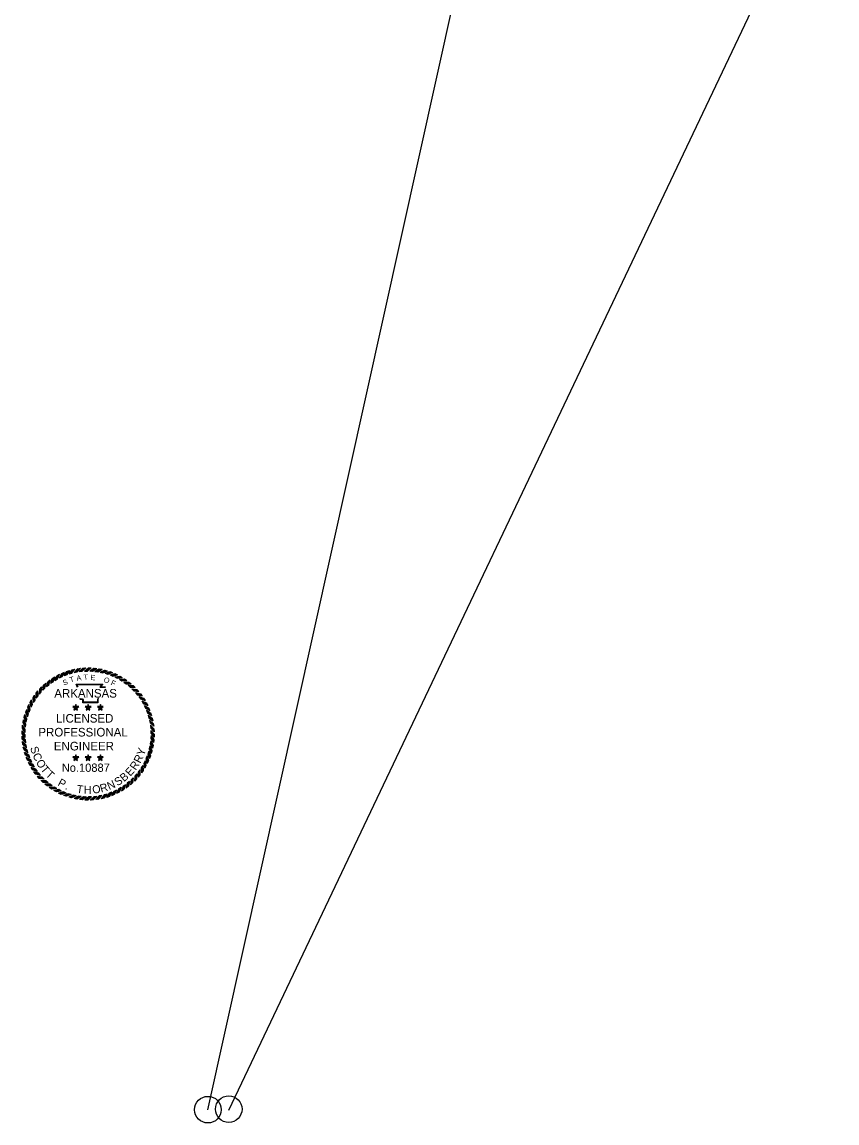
# Model space of a CAD drawing. Extents: x -12863 to 18921, y -8840 to 11152.
# Drawn here: x 3046 to 4579, y -284 to 1785 of the extents above; entities that cross this region are included whole.
import ezdxf

# ---------------------------------------------------------------- set-up
doc = ezdxf.new("R2010")
doc.units = 0
doc.layers.add('Level 46', color=7, linetype='Continuous')
doc.layers.add('Level 48', color=7, linetype='Continuous')

msp = doc.modelspace()

# ---------------------------------------------------------------- linework, layer by layer
at = {"layer": 'Level 46'}
for p, q in [((3112.2, 556.8), (3117, 559.5)), ((3121.4, 561.3), (3126.4, 563.5)), ((3125.9, 557), (3131.1, 558.9)), ((3131, 565), (3136.1, 566.8)), ((3135.1, 560.4), (3140.4, 561.8)), ((3140.9, 567.9), (3146.1, 569.2)), ((3144.6, 562.9), (3150, 563.9)), ((3150.9, 569.9), (3156.3, 570.9)), ((3154.2, 564.7), (3159.7, 565.2)), ((3161.1, 571.1), (3166.5, 571.6)), ((3164, 565.6), (3169.4, 565.6)), ((3171.4, 571.4), (3176.8, 571.4)), ((3173.7, 565.8), (3179.2, 565.4)), ((3181.6, 571), (3187, 570.6)), ((3183.5, 565.1), (3188.9, 564.3)), ((3191.7, 569.7), (3197.1, 568.9)), ((3193.2, 563.7), (3198.5, 562.4)), ((3201.8, 567.5), (3207.1, 566.3)), ((3202.7, 561.4), (3207.9, 559.7)), ((3211.6, 564.6), (3216.8, 562.9)), ((3221.1, 560.8), (3226.1, 558.7)), ((3087.1, 539.1), (3091.1, 542.9)), ((3092.8, 536.6), (3097, 540)), ((3095, 545.7), (3099.2, 549.1)), ((3100.4, 542.7), (3104.9, 545.7)), ((3103.4, 551.6), (3107.9, 554.7)), ((3108.5, 548.2), (3113.3, 550.8)), ((3117, 553), (3122, 555.2)), ((3212, 558.4), (3217, 556.2)), ((3221, 554.6), (3225.9, 552)), ((3229.7, 550.1), (3234.3, 547.1)), ((3230.3, 556.2), (3235.1, 553.7)), ((3238, 544.9), (3242.3, 541.5)), ((3239.1, 550.9), (3243.7, 548)), ((3245.8, 539), (3249.9, 535.3)), ((3247.4, 544.9), (3251.7, 541.6)), ((3255.2, 538.3), (3259.2, 534.6)), ((3067.2, 515.8), (3070.1, 520.4)), ((3073.2, 524.1), (3076.5, 528.5)), ((3073.3, 514.7), (3076.6, 519)), ((3079.2, 522.5), (3082.8, 526.6)), ((3079.8, 531.9), (3083.5, 536)), ((3085.7, 529.8), (3089.6, 533.6)), ((3253.1, 532.4), (3256.8, 528.5)), ((3259.9, 525.3), (3263.2, 521.1)), ((3262.4, 531), (3266.1, 527)), ((3266, 517.7), (3269, 513.2)), ((3269, 523.1), (3272.4, 518.9)), ((3057.3, 497.8), (3059.5, 502.8)), ((3061.9, 507), (3064.4, 511.8)), ((3063.5, 497.8), (3066.1, 502.6)), ((3068, 506.4), (3071, 511)), ((3153.1, 498.8), (3142.1, 498.8)), ((3142.1, 498.8), (3151, 492.3)), ((3147.6, 502.8), (3144.2, 492.3)), ((3144.2, 492.3), (3153.1, 498.8)), ((3146.8, 497), (3148.5, 497)), ((3151, 492.3), (3147.6, 502.8)), ((3147.6, 497.6), (3147.6, 496.3)), ((3176.2, 498.8), (3165.2, 498.8)), ((3165.2, 498.8), (3174.1, 492.3)), ((3170.7, 502.8), (3167.3, 492.3)), ((3167.3, 492.3), (3176.2, 498.8)), ((3169.9, 497), (3171.5, 497)), ((3174.1, 492.3), (3170.7, 502.8)), ((3170.7, 497.6), (3170.7, 496.3)), ((3199.3, 498.8), (3188.3, 498.8)), ((3188.3, 498.8), (3197.2, 492.3)), ((3193.8, 502.8), (3190.4, 492.3)), ((3190.4, 492.3), (3199.3, 498.8)), ((3193, 497), (3194.6, 497)), ((3197.2, 492.3), (3193.8, 502.8)), ((3193.8, 497.6), (3193.8, 496.3)), ((3271.5, 509.6), (3274.1, 504.8)), ((3274.9, 514.8), (3277.9, 510.2)), ((3276.3, 501.1), (3278.5, 496.1)), ((3280.1, 505.9), (3282.8, 501.2)), ((3284.6, 496.7), (3286.8, 491.7)), ((3050.6, 478.5), (3051.9, 483.8)), ((3053.5, 488.3), (3055.3, 493.5)), ((3056.7, 479.4), (3058.4, 484.6)), ((3059.7, 488.7), (3061.9, 493.7)), ((3280.3, 492.2), (3282.2, 487)), ((3283.7, 483), (3285, 477.7)), ((3288.3, 487.1), (3290.1, 482)), ((3291.1, 477.3), (3292.5, 472)), ((3047.1, 458.3), (3047.5, 463.7)), ((3048.4, 468.5), (3049.3, 473.8)), ((3052.3, 450.5), (3052.7, 455.9)), ((3053, 460.2), (3053.8, 465.6)), ((3054.4, 469.9), (3055.7, 475.2)), ((3286.2, 473.5), (3287.2, 468.1)), ((3288, 463.9), (3288.5, 458.5)), ((3293.2, 467.2), (3294.1, 461.9)), ((3294.4, 457), (3294.9, 451.6)), ((3047, 437.8), (3046.5, 443.2)), ((3046.6, 448), (3046.6, 453.5)), ((3052.5, 440.7), (3052.4, 446.1)), ((3053.4, 430.9), (3052.9, 436.4)), ((3288.4, 434.6), (3287.6, 429.2)), ((3289.1, 444.4), (3288.7, 438.9)), ((3288.9, 454.2), (3289, 448.7)), ((3294.3, 436.5), (3293.9, 431.1)), ((3294.8, 446.8), (3294.8, 441.3)), ((3048.2, 427.6), (3047.3, 433)), ((3050.3, 417.6), (3048.9, 422.8)), ((3055.2, 421.3), (3054.2, 426.7)), ((3057.7, 411.9), (3056.4, 417.1)), ((3284.7, 415.4), (3283, 410.2)), ((3287, 424.9), (3285.7, 419.6)), ((3290.8, 416.3), (3289.5, 411.1)), ((3293, 426.4), (3292.1, 421)), ((3053.1, 407.7), (3051.3, 412.9)), ((3056.8, 398.1), (3054.6, 403.1)), ((3061.3, 388.9), (3058.6, 393.7)), ((3061.1, 402.7), (3059.2, 407.8)), ((3065.1, 393.8), (3062.9, 398.7)), ((3153.1, 404.2), (3142.1, 404.2)), ((3142.1, 404.2), (3151, 397.7)), ((3147.6, 408.2), (3144.2, 397.7)), ((3144.2, 397.7), (3153.1, 404.2)), ((3146.8, 402.4), (3148.5, 402.4)), ((3151, 397.7), (3147.6, 408.2)), ((3147.6, 403), (3147.6, 401.6)), ((3176.2, 404.2), (3165.2, 404.2)), ((3165.2, 404.2), (3174.1, 397.7)), ((3170.7, 408.2), (3167.3, 397.7)), ((3167.3, 397.7), (3176.2, 404.2)), ((3169.9, 402.4), (3171.5, 402.4)), ((3174.1, 397.7), (3170.7, 408.2)), ((3170.7, 403), (3170.7, 401.6)), ((3199.3, 404.2), (3188.3, 404.2)), ((3188.3, 404.2), (3197.2, 397.7)), ((3193.8, 408.2), (3190.4, 397.7)), ((3190.4, 397.7), (3199.3, 404.2)), ((3193, 402.4), (3194.6, 402.4)), ((3197.2, 397.7), (3193.8, 408.2)), ((3193.8, 403), (3193.8, 401.6)), ((3277.9, 397.1), (3275.3, 392.2)), ((3281.7, 406.1), (3279.5, 401.1)), ((3284.1, 397), (3281.9, 392)), ((3287.9, 406.5), (3286.1, 401.4)), ((3066.5, 380.1), (3063.5, 384.6)), ((3069.9, 385.2), (3067.3, 390)), ((3072.4, 371.7), (3069, 376)), ((3075.4, 377.1), (3072.4, 381.6)), ((3081.5, 369.5), (3078.1, 373.8)), ((3268.1, 380.1), (3264.8, 375.8)), ((3273.4, 388.4), (3270.4, 383.8)), ((3274.2, 379), (3271.3, 374.4)), ((3279.5, 387.8), (3277, 383)), ((3079, 363.8), (3075.3, 367.8)), ((3086.2, 356.5), (3082.2, 360.2)), ((3088.3, 362.4), (3084.5, 366.4)), ((3094, 349.9), (3089.7, 353.2)), ((3095.6, 355.9), (3091.5, 359.5)), ((3103.4, 350), (3099.1, 353.3)), ((3241, 352.1), (3236.5, 349.1)), ((3248.6, 358.3), (3244.4, 354.9)), ((3254.3, 355.7), (3250.3, 352)), ((3255.7, 365), (3251.8, 361.3)), ((3261.6, 362.9), (3257.9, 358.9)), ((3262.2, 372.3), (3258.6, 368.3)), ((3268.2, 370.7), (3264.9, 366.4)), ((3102.3, 343.9), (3097.7, 346.8)), ((3111.1, 338.6), (3106.3, 341.1)), ((3111.7, 344.8), (3107.1, 347.7)), ((3120.3, 334), (3115.3, 336.2)), ((3120.4, 340.2), (3115.5, 342.8)), ((3129.4, 336.4), (3124.4, 338.6)), ((3129.8, 330.3), (3124.6, 332)), ((3138.7, 333.4), (3133.5, 335.1)), ((3148.2, 331.1), (3142.9, 332.4)), ((3196.8, 331.9), (3191.4, 331)), ((3206.3, 334.5), (3201, 333.1)), ((3215.5, 337.8), (3210.3, 336)), ((3220, 333.5), (3215, 331.3)), ((3224.4, 341.8), (3219.4, 339.6)), ((3229.2, 338), (3224.4, 335.3)), ((3232.9, 346.6), (3228.1, 344)), ((3238, 343.2), (3233.5, 340.2)), ((3246.4, 349.1), (3242.2, 345.7)), ((3139.6, 327.3), (3134.3, 328.6)), ((3149.6, 325.1), (3144.3, 326)), ((3157.9, 329.7), (3152.5, 330.5)), ((3159.8, 323.8), (3154.4, 324.2)), ((3167.7, 329), (3162.2, 329.4)), ((3170.1, 323.3), (3164.6, 323.3)), ((3177.4, 329.2), (3172, 329.1)), ((3180.3, 323.7), (3174.9, 323.2)), ((3187.2, 330.1), (3181.7, 329.6)), ((3190.5, 324.9), (3185.1, 324)), ((3200.5, 327), (3195.3, 325.6)), ((3210.4, 329.8), (3205.3, 328))]:
    msp.add_line(p, q, dxfattribs=at)
for points in [[(3111.7, 550), (3115.4, 558.6)], [(3113.3, 550.8), (3117, 559.5)], [(3117, 553), (3121.4, 561.3)], [(3118.6, 553.7), (3123, 562)], [(3120.3, 554.5), (3124.7, 562.8)], [(3122, 555.2), (3126.4, 563.5)], [(3125.9, 557), (3131, 565)], [(3127.6, 557.6), (3132.7, 565.5)], [(3129.4, 558.3), (3134.4, 566.2)], [(3131.1, 558.9), (3136.1, 566.8)], [(3135.1, 560.4), (3140.8, 567.9)], [(3136.8, 560.8), (3142.5, 568.3)], [(3138.7, 561.3), (3144.4, 568.8)], [(3140.4, 561.8), (3146.1, 569.2)], [(3144.6, 562.9), (3150.9, 569.9)], [(3146.3, 563.2), (3152.6, 570.2)], [(3148.2, 563.6), (3154.5, 570.6)], [(3150, 563.9), (3156.3, 570.9)], [(3154.2, 564.7), (3161.1, 571.1)], [(3156, 564.8), (3162.8, 571.3)], [(3157.8, 565), (3164.7, 571.5)], [(3159.6, 565.2), (3166.5, 571.6)], [(3164, 565.6), (3171.4, 571.4)], [(3165.7, 565.6), (3173.1, 571.4)], [(3167.6, 565.7), (3175, 571.5)], [(3169.4, 565.6), (3176.8, 571.4)], [(3173.7, 565.8), (3181.6, 571)], [(3175.5, 565.6), (3183.3, 570.9)], [(3177.4, 565.5), (3185.2, 570.8)], [(3179.2, 565.4), (3187, 570.6)], [(3183.5, 565.1), (3191.7, 569.7)], [(3185.2, 564.8), (3193.5, 569.4)], [(3187.1, 564.6), (3195.3, 569.2)], [(3188.9, 564.3), (3197.1, 568.9)], [(3193.2, 563.7), (3201.8, 567.5)], [(3194.9, 563.2), (3203.5, 567.1)], [(3196.7, 562.8), (3205.3, 566.7)], [(3198.5, 562.4), (3207.1, 566.3)], [(3202.7, 561.4), (3211.6, 564.6)], [(3204.4, 560.9), (3213.2, 564)], [(3206.2, 560.3), (3215, 563.4)], [(3207.9, 559.7), (3216.8, 562.9)], [(3212, 558.4), (3221.1, 560.8)], [(3213.6, 557.7), (3222.7, 560.1)], [(3215.4, 557), (3224.5, 559.4)], [(3217, 556.3), (3226.1, 558.7)], [(3085.7, 529.8), (3087.1, 539.1)], [(3087, 531), (3088.4, 540.3)], [(3088.3, 532.3), (3089.8, 541.6)], [(3089.6, 533.6), (3091.1, 542.9)], [(3092.8, 536.6), (3095, 545.7)], [(3094.1, 537.6), (3096.4, 546.8)], [(3095.6, 538.8), (3097.8, 548)], [(3097, 540), (3099.2, 549.1)], [(3100.4, 542.7), (3103.4, 551.6)], [(3101.9, 543.7), (3104.8, 552.6)], [(3103.4, 544.7), (3106.4, 553.7)], [(3104.9, 545.7), (3107.9, 554.7)], [(3108.5, 548.2), (3112.2, 556.8)], [(3110, 549), (3113.7, 557.7)], [(3151.1, 535), (3148.2, 541.3), (3198.4, 541.3), (3194.2, 536.1), (3197.6, 536.1), (3200.5, 536.1), (3203.3, 535.8)], [(3151.8, 535.4), (3149.5, 540.5), (3196.7, 540.5), (3192.5, 535.2), (3197.6, 535.3), (3200.4, 535.3), (3203.2, 535)], [(3221, 554.6), (3230.3, 556.2)], [(3222.6, 553.8), (3231.8, 555.4)], [(3224.3, 552.9), (3233.5, 554.6)], [(3225.9, 552.1), (3235.1, 553.7)], [(3229.7, 550.1), (3239.1, 550.9)], [(3231.2, 549.1), (3240.6, 550)], [(3232.8, 548.1), (3242.2, 549)], [(3234.3, 547.1), (3243.7, 548)], [(3238, 544.9), (3247.4, 544.9)], [(3239.4, 543.8), (3248.8, 543.9)], [(3240.9, 542.7), (3250.3, 542.8)], [(3242.3, 541.5), (3251.7, 541.6)], [(3245.8, 539), (3255.2, 538.3)], [(3069, 507.9), (3068.1, 517.3)], [(3070, 509.5), (3069.1, 518.9)], [(3071, 511), (3070.1, 520.4)], [(3073.3, 514.7), (3073.2, 524.1)], [(3074.3, 516.1), (3074.2, 525.5)], [(3075.4, 517.6), (3075.4, 527)], [(3076.6, 519), (3076.5, 528.5)], [(3079.2, 522.5), (3079.8, 531.9)], [(3080.3, 523.8), (3081, 533.2)], [(3081.6, 525.2), (3082.3, 534.6)], [(3082.8, 526.6), (3083.5, 536)], [(3247.1, 537.8), (3256.5, 537.1)], [(3248.5, 536.5), (3257.9, 535.9)], [(3249.9, 535.3), (3259.2, 534.6)], [(3253.1, 532.4), (3262.4, 531)], [(3254.3, 531.2), (3263.6, 529.7)], [(3255.6, 529.8), (3264.9, 528.4)], [(3256.8, 528.5), (3266.1, 527)], [(3259.9, 525.4), (3269, 523.1)], [(3260.9, 524), (3270.1, 521.8)], [(3262.1, 522.5), (3271.3, 520.3)], [(3263.2, 521.1), (3272.4, 518.9)], [(3266, 517.7), (3274.9, 514.8)], [(3059.7, 488.7), (3057.3, 497.8)], [(3060.4, 490.3), (3058, 499.4)], [(3061.1, 492.1), (3058.7, 501.2)], [(3061.9, 493.7), (3059.5, 502.8)], [(3063.5, 497.8), (3061.9, 507)], [(3064.3, 499.3), (3062.7, 508.6)], [(3065.2, 501), (3063.5, 510.3)], [(3066.1, 502.6), (3064.4, 511.8)], [(3068, 506.4), (3067.2, 515.8)], [(3190.5, 514), (3189.6, 513.3), (3189.3, 512.3), (3189.1, 509.7), (3189.1, 506.2), (3161.1, 506.2), (3161.1, 510.9), (3161.1, 511.9), (3159.9, 512.3), (3155.9, 512.3), (3155.2, 513.3)], [(3190, 514.6), (3188.9, 513.7), (3188.6, 512.4), (3188.3, 509.7), (3188.3, 507), (3161.8, 507), (3161.8, 510.9), (3161.8, 512.5), (3160, 513), (3156.4, 513), (3155.9, 513.8)], [(3266.9, 516.3), (3275.9, 513.3)], [(3268, 514.7), (3277, 511.7)], [(3269, 513.2), (3278, 510.2)], [(3271.5, 509.6), (3280.1, 505.9)], [(3272.3, 508.1), (3281, 504.4)], [(3273.2, 506.4), (3281.9, 502.7)], [(3274.1, 504.8), (3282.8, 501.2)], [(3276.3, 501.1), (3284.6, 496.7)], [(3277, 499.5), (3285.3, 495.1)], [(3277.8, 497.8), (3286.1, 493.4)], [(3054.4, 469.9), (3050.6, 478.5)], [(3054.9, 471.6), (3051, 480.2)], [(3055.3, 473.4), (3051.4, 482)], [(3055.7, 475.2), (3051.8, 483.8)], [(3056.7, 479.4), (3053.5, 488.3)], [(3057.3, 481.1), (3054.1, 490)], [(3057.8, 482.9), (3054.7, 491.8)], [(3058.4, 484.6), (3055.3, 493.5)], [(3278.5, 496.1), (3286.8, 491.7)], [(3280.3, 492.2), (3288.3, 487.1)], [(3280.9, 490.5), (3288.8, 485.5)], [(3281.6, 488.8), (3289.5, 483.7)], [(3282.2, 487), (3290.1, 482)], [(3283.6, 483), (3291.1, 477.3)], [(3284.1, 481.3), (3291.6, 475.6)], [(3284.6, 479.5), (3292.1, 473.8)], [(3285, 477.7), (3292.5, 472)], [(3052.3, 450.5), (3047.1, 458.3)], [(3052.5, 452.2), (3047.2, 460)], [(3052.6, 454.1), (3047.3, 461.9)], [(3052.7, 455.9), (3047.5, 463.7)], [(3053, 460.2), (3048.4, 468.5)], [(3053.3, 461.9), (3048.7, 470.2)], [(3053.5, 463.8), (3049, 472.1)], [(3053.8, 465.6), (3049.3, 473.8)], [(3286.2, 473.5), (3293.2, 467.2)], [(3286.5, 471.8), (3293.5, 465.5)], [(3286.9, 469.9), (3293.8, 463.6)], [(3287.2, 468.2), (3294.1, 461.9)], [(3288, 463.9), (3294.4, 457)], [(3288.1, 462.2), (3294.6, 455.3)], [(3288.3, 460.3), (3294.8, 453.4)], [(3288.5, 458.5), (3294.9, 451.6)], [(3052.9, 436.4), (3046.5, 443.2)], [(3052.4, 446.1), (3046.6, 453.5)], [(3052.4, 444.3), (3046.6, 451.7)], [(3052.5, 442.4), (3046.6, 449.8)], [(3052.5, 440.7), (3046.6, 448)], [(3053.1, 434.6), (3046.6, 441.4)], [(3053.3, 432.7), (3046.8, 439.5)], [(3053.4, 430.9), (3047, 437.8)], [(3288.4, 434.6), (3293, 426.4)], [(3288.7, 438.9), (3293.9, 431.1)], [(3288.8, 440.7), (3294.1, 432.9)], [(3288.9, 454.2), (3294.8, 446.8)], [(3288.9, 452.4), (3294.8, 445)], [(3288.9, 442.6), (3294.2, 434.8)], [(3289, 450.5), (3294.8, 443.1)], [(3289, 448.7), (3294.8, 441.3)], [(3289.1, 444.4), (3294.3, 436.5)], [(3054.2, 426.7), (3047.2, 433)], [(3054.5, 424.9), (3047.5, 431.2)], [(3054.9, 423), (3047.9, 429.3)], [(3055.2, 421.3), (3048.2, 427.6)], [(3056.4, 417.1), (3048.9, 422.8)], [(3056.8, 415.4), (3049.3, 421.1)], [(3057.3, 413.6), (3049.8, 419.3)], [(3057.7, 411.9), (3050.3, 417.6)], [(3284.1, 413.7), (3287.3, 404.9)], [(3284.7, 415.4), (3287.9, 406.5)], [(3285.7, 419.6), (3289.5, 411)], [(3286.1, 421.4), (3290, 412.8)], [(3286.5, 423.2), (3290.4, 414.6)], [(3287, 424.9), (3290.8, 416.3)], [(3287.6, 429.2), (3292.1, 421)], [(3287.9, 431), (3292.4, 422.8)], [(3288.1, 432.9), (3292.7, 424.6)], [(3059.2, 407.8), (3051.3, 412.9)], [(3059.8, 406.1), (3051.9, 411.1)], [(3060.5, 404.3), (3052.6, 409.4)], [(3061.1, 402.6), (3053.1, 407.7)], [(3062.9, 398.7), (3054.6, 403.1)], [(3063.6, 397.1), (3055.3, 401.5)], [(3064.4, 395.4), (3056.1, 399.7)], [(3065.1, 393.7), (3056.8, 398.1)], [(3067.3, 390), (3058.6, 393.7)], [(3276.2, 393.8), (3277.8, 384.6)], [(3277.1, 395.5), (3278.7, 386.3)], [(3277.9, 397.1), (3279.5, 387.8)], [(3279.5, 401.1), (3281.9, 392)], [(3280.3, 402.7), (3282.7, 393.6)], [(3281, 404.5), (3283.4, 395.4)], [(3281.7, 406.1), (3284.1, 397)], [(3283, 410.2), (3286.1, 401.4)], [(3283.6, 411.9), (3286.7, 403.1)], [(3068.1, 388.4), (3059.5, 392.1)], [(3069.1, 386.8), (3060.4, 390.4)], [(3069.9, 385.2), (3061.3, 388.9)], [(3072.4, 381.6), (3063.4, 384.6)], [(3073.4, 380.1), (3064.4, 383.1)], [(3074.5, 378.6), (3065.5, 381.5)], [(3075.4, 377.1), (3066.5, 380.1)], [(3078.1, 373.7), (3069, 376)], [(3079.3, 372.3), (3070.1, 374.5)], [(3080.5, 370.9), (3071.3, 373.1)], [(3264.8, 375.8), (3264.9, 366.4)], [(3265.9, 377.2), (3266, 367.8)], [(3267.1, 378.7), (3267.2, 369.3)], [(3268.1, 380.1), (3268.2, 370.7)], [(3270.4, 383.8), (3271.3, 374.4)], [(3271.4, 385.3), (3272.3, 375.9)], [(3272.4, 386.9), (3273.3, 377.6)], [(3273.4, 388.4), (3274.2, 379)], [(3275.3, 392.3), (3277, 383)], [(3081.5, 369.5), (3072.4, 371.7)], [(3084.5, 366.4), (3075.2, 367.8)], [(3085.8, 365), (3076.5, 366.5)], [(3087.1, 363.7), (3077.8, 365.1)], [(3088.3, 362.4), (3079, 363.8)], [(3091.5, 359.5), (3082.1, 360.2)], [(3092.9, 358.3), (3083.5, 359)], [(3094.3, 357.1), (3084.9, 357.7)], [(3095.6, 355.9), (3086.2, 356.5)], [(3099.1, 353.3), (3089.7, 353.2)], [(3100.5, 352.2), (3091.1, 352.1)], [(3241, 352.1), (3238, 343.2)], [(3244.4, 354.9), (3242.2, 345.7)], [(3245.8, 356), (3243.6, 346.8)], [(3247.3, 357.2), (3245, 348)], [(3248.6, 358.3), (3246.4, 349.1)], [(3251.8, 361.3), (3250.3, 352)], [(3253.1, 362.5), (3251.6, 353.2)], [(3254.4, 363.8), (3253, 354.5)], [(3255.7, 365), (3254.3, 355.7)], [(3258.6, 368.3), (3257.9, 358.9)], [(3259.8, 369.6), (3259.1, 360.2)], [(3261.1, 371), (3260.4, 361.6)], [(3262.2, 372.3), (3261.6, 362.9)], [(3102, 351.1), (3092.6, 351)], [(3103.4, 350), (3094, 349.9)], [(3107.1, 347.7), (3097.7, 346.8)], [(3108.6, 346.7), (3099.2, 345.8)], [(3110.2, 345.7), (3100.8, 344.8)], [(3111.7, 344.8), (3102.3, 343.9)], [(3115.5, 342.8), (3106.3, 341.1)], [(3117.1, 341.9), (3107.9, 340.3)], [(3118.8, 341.1), (3109.6, 339.4)], [(3120.4, 340.2), (3111.1, 338.6)], [(3124.4, 338.6), (3115.3, 336.2)], [(3126, 337.8), (3116.9, 335.4)], [(3127.8, 337.1), (3118.7, 334.7)], [(3129.4, 336.4), (3120.3, 334)], [(3133.5, 335.1), (3124.6, 332)], [(3135.2, 334.5), (3126.4, 331.4)], [(3137, 334), (3128.2, 330.8)], [(3138.7, 333.4), (3129.8, 330.3)], [(3142.9, 332.4), (3134.3, 328.6)], [(3144.7, 332), (3136.1, 328.1)], [(3146.5, 331.6), (3137.9, 327.7)], [(3148.2, 331.2), (3139.6, 327.3)], [(3193.2, 331.3), (3186.9, 324.3)], [(3195.1, 331.6), (3188.8, 324.6)], [(3196.8, 331.9), (3190.5, 324.9)], [(3201, 333.1), (3195.3, 325.6)], [(3202.7, 333.5), (3197, 326)], [(3204.6, 334), (3198.9, 326.5)], [(3206.3, 334.5), (3200.6, 327)], [(3210.3, 336), (3205.3, 328)], [(3212, 336.5), (3207, 328.6)], [(3213.8, 337.2), (3208.7, 329.3)], [(3215.5, 337.8), (3210.4, 329.9)], [(3219.4, 339.6), (3215, 331.3)], [(3221.1, 340.3), (3216.7, 332)], [(3222.8, 341.2), (3218.4, 332.8)], [(3224.4, 341.9), (3220, 333.5)], [(3228.1, 344), (3224.4, 335.3)], [(3229.7, 344.9), (3226, 336.2)], [(3231.4, 345.8), (3227.7, 337.2)], [(3232.9, 346.6), (3229.2, 338)], [(3236.5, 349.1), (3233.5, 340.2)], [(3238, 350.1), (3235, 341.2)], [(3239.5, 351.2), (3236.6, 342.2)], [(3152.5, 330.5), (3144.3, 326)], [(3154.3, 330.2), (3146.1, 325.7)], [(3156.2, 330), (3147.9, 325.4)], [(3157.9, 329.7), (3149.7, 325.1)], [(3162.2, 329.4), (3154.4, 324.2)], [(3164, 329.3), (3156.2, 324)], [(3165.9, 329.2), (3158.1, 324)], [(3167.7, 329), (3159.8, 323.8)], [(3172, 329.1), (3164.6, 323.3)], [(3173.8, 329.1), (3166.4, 323.3)], [(3175.7, 329.2), (3168.3, 323.3)], [(3177.4, 329.2), (3170.1, 323.3)], [(3181.8, 329.6), (3174.9, 323.2)], [(3183.6, 329.8), (3176.7, 323.3)], [(3185.4, 330), (3178.6, 323.6)], [(3187.2, 330.1), (3180.3, 323.7)], [(3191.4, 331), (3185.1, 324)]]:
    msp.add_lwpolyline(points, dxfattribs=at)
at = {"layer": 'Level 48'}
for p, q in [((3396, -258.5), (4135.1, 3074.7)), ((3435.5, -259.2), (5021.7, 3074.7))]:
    msp.add_line(p, q, dxfattribs=at)
for centre in [(3396, -258.5), (3435.1, -257.5)]:
    msp.add_circle(centre, 25, dxfattribs=at)

# ---------------------------------------------------------------- texts
at = {"layer": 'Level 46'}
for s, height, rotation, p in [('T', 9.9, 1.4789, (3162.4, 549.1)), ('E', 9.9, 356.672, (3175, 548.8)), ('S', 9.9, 19.7726, (3125, 538.3)), ('T', 9.9, 16.9015, (3137.6, 544)), ('A', 9.9, 8.6788, (3149.6, 547.1)), ('O', 9.9, 341.2218, (3199.1, 545.4)), ('F', 9.9, 335.3628, (3212.4, 540.2)), ('S', 15, 286.9475, (3061.6, 421.5)), ('Y', 15, 71.7733, (3275.8, 405.4)), ('C', 15, 294.2435, (3065.8, 407.8)), ('O', 15, 301.9044, (3072, 394.1)), ('R', 15, 55.7221, (3260.1, 378.2)), ('R', 15, 63.7477, (3268.9, 391.2)), ('T', 15, 309.93, (3080.4, 380.7)), ('T', 15, 317.226, (3089.6, 369.7)), ('B', 15, 40.0357, (3238.1, 356.7)), ('E', 15, 48.0613, (3250.1, 366.9)), ('P', 15, 332.1828, (3112.4, 351.3)), ('T', 15, 351.882, (3148.3, 337.1)), ('R', 15, 15.9589, (3195.3, 337.3)), ('N', 15, 23.9845, (3210.4, 341.8)), ('S', 15, 32.7397, (3226, 349)), ('.', 15, 340.2084, (3126.4, 344)), ('H', 15, 359.178, (3162.5, 335.1)), ('O', 15, 7.9332, (3179.7, 335.1))]:
    msp.add_text(s, height=height, rotation=rotation, dxfattribs=at).set_placement(p)
for s, height, p in [('ARKANSAS', 16.15, (3107.2, 515.8)), ('LICENSED', 16.15, (3110.3, 468.8)), ('PROFESSIONAL', 16.155, (3077.2, 442.7)), ('ENGINEER', 16.15, (3106.4, 416.5)), ('No.10887', 15.58, (3121.2, 376.3))]:
    msp.add_text(s, height=height, dxfattribs=at).set_placement(p)

doc.saveas('drawing.dxf')
